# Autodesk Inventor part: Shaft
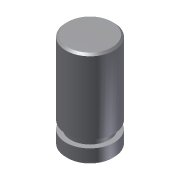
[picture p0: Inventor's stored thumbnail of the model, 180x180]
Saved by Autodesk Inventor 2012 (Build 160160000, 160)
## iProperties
Created: 2008-06
Part Number: Shaft
Document SubType Name: Modeling
Designer: CADCIM
Density: 1 g/cm^3
Material: Default
Author: CADCIM
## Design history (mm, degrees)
sketch "Sketch1"
  geometry: C1 r 25 at (0, 0); 1 further point
  constraints: 1 centre point, 1 coincident, 1 other
  dimensions: "d0" = 50 diameter of C1
extrude "Extrusion1" new body sketch "Sketch1" distance "d1" = 100; taper "d2" = 0 deg
chamfer "Chamfer1" distance "d3" = 2; stored, may be unused: second distance "d4" = 2, angle "d5" = 45 deg
sketch "Sketch2"
  geometry: L1 (-25, 23)-(-20, 23); L2 (-20, 23)-(-20, 15); L3 (-20, 15)-(-25, 15); L4 (-25, 15)-(-25, 23); L5 (0, -1.4)-(0, 8.4) reference; 1 further point
  constraints: 8 end point, 2 parallel, 1 horizontal, 1 perpendicular, 1 point on line, 1 other
  dimensions: "d9" = 8 distance of L3.end L1.start; "d10" = 20 distance from line of point (0, 0) L2; "d11" = 15 distance from line of L3 point (0, 0); "d13" = 25 distance from line of point (0, 0) L4
revolve "Revolution1" sketch "Sketch2" stored, may be unused: angle "d12" = 90 deg
body "Solid1"
other parameters: "d21" = 0
